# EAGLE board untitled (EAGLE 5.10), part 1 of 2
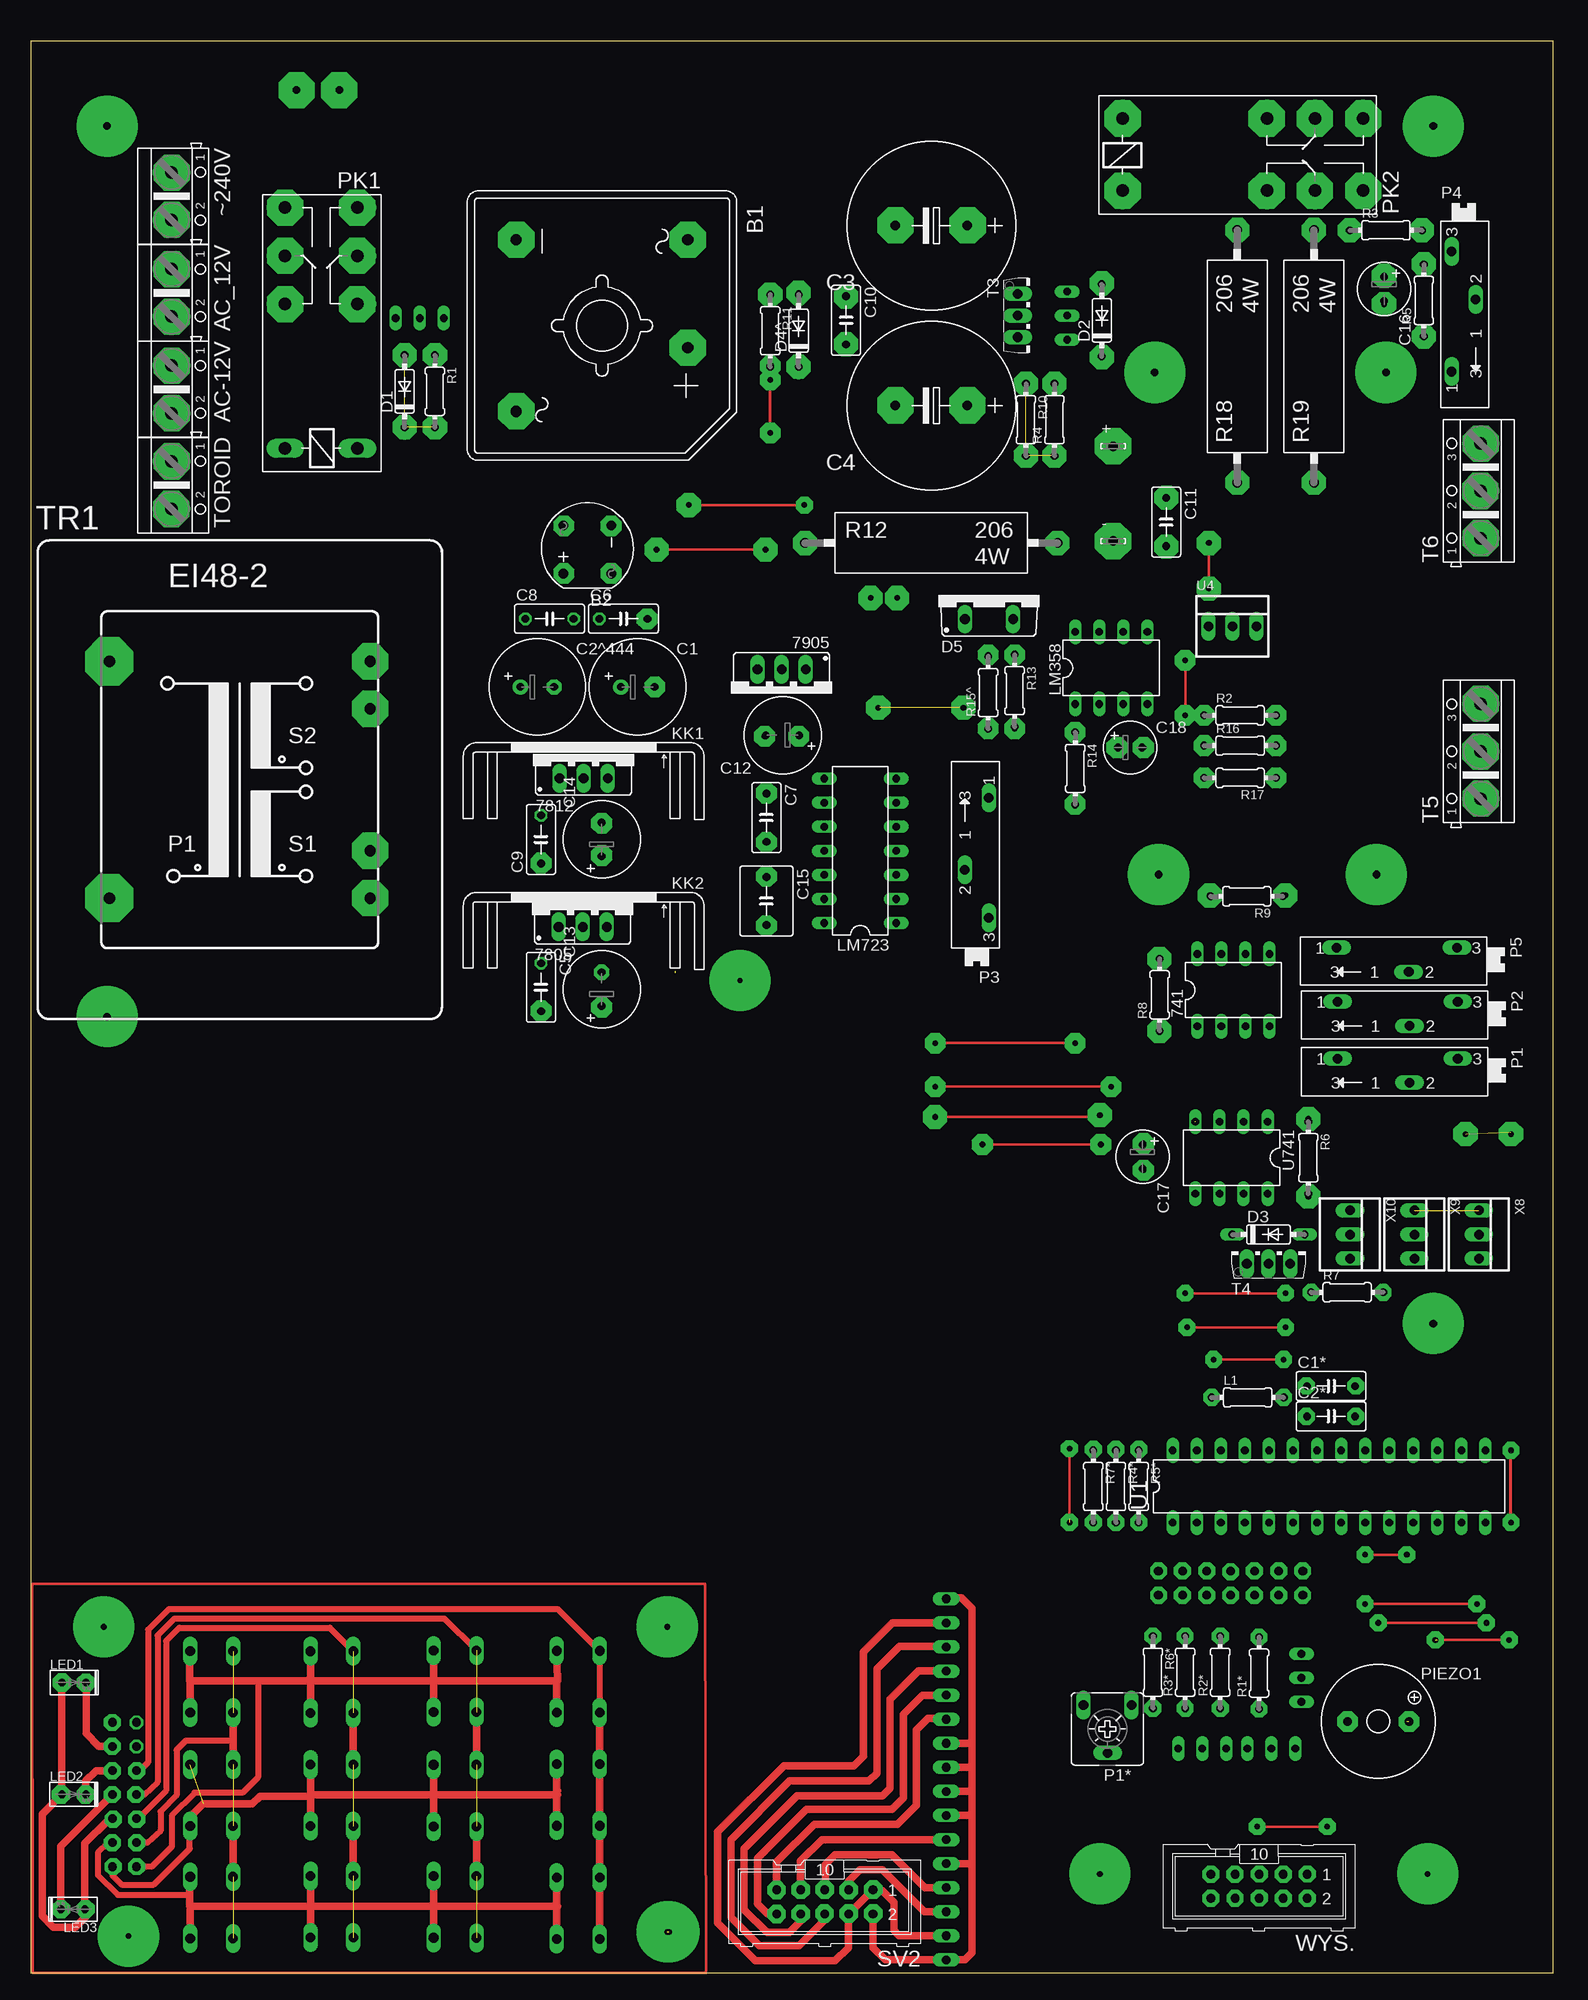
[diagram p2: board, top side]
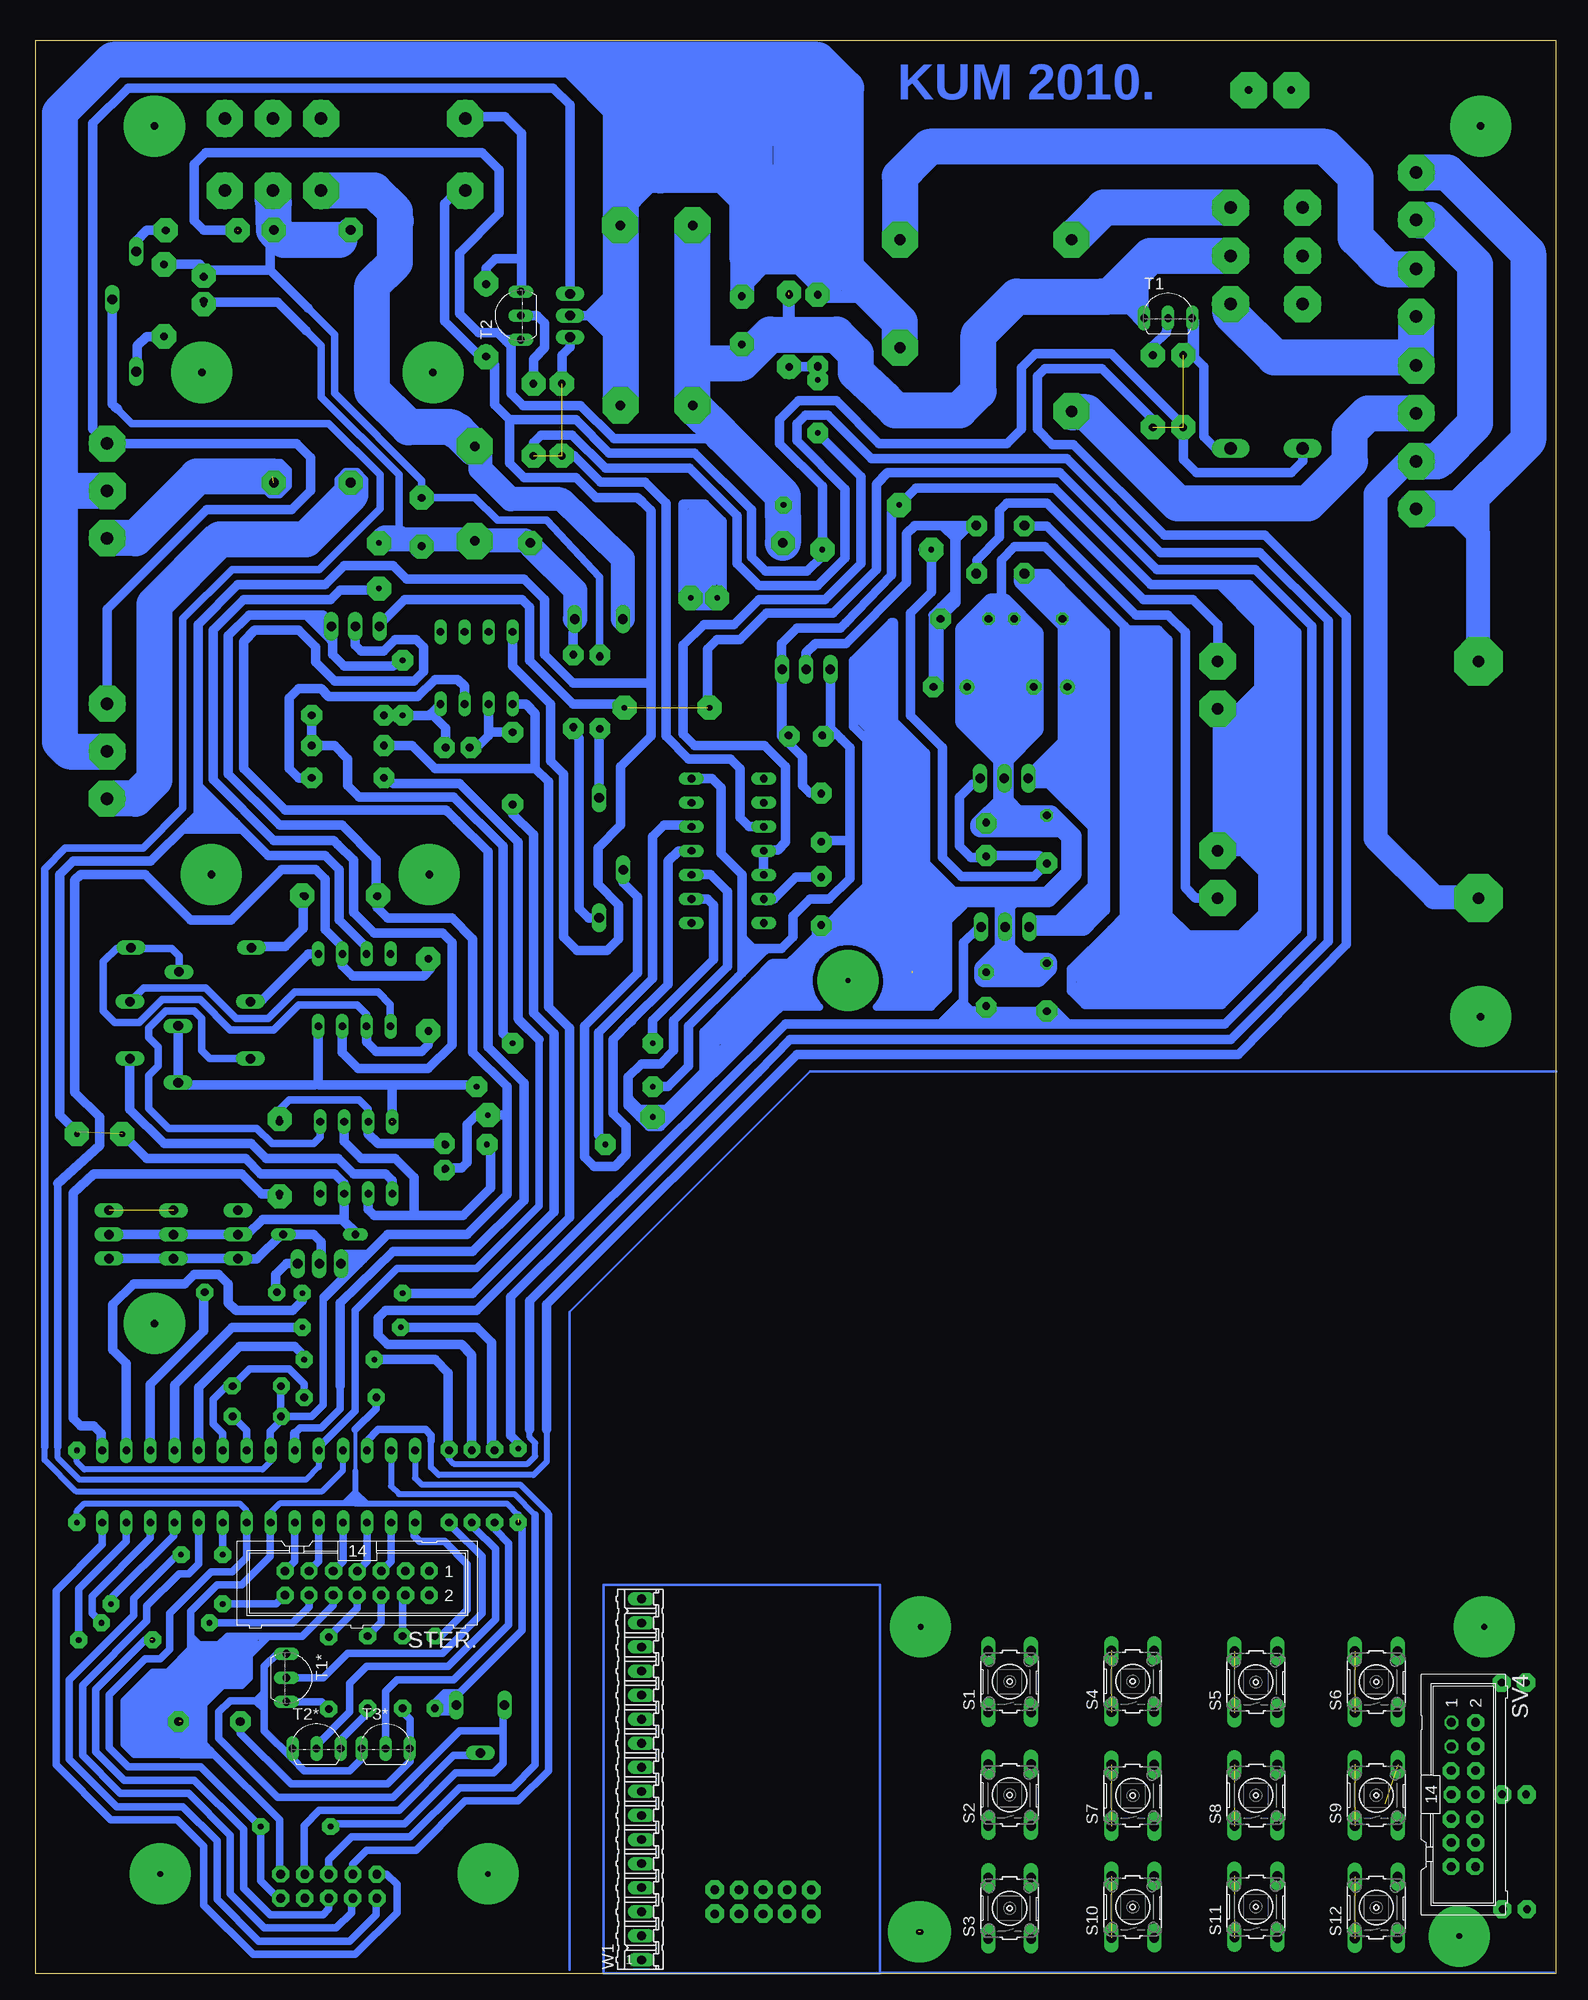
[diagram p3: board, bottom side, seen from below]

Size 160.6 x 204 mm. Coordinates in mm from the lower left corner, seen from the top.
Outline: 0,204 160.6,204 160.6,0 0,0 0,204
Copper layers (1*16): Top 0.035mm / dielectric 1.5mm / Bottom 0.035mm
Design rules "default": minimum track width 10mil, minimum drill 24mil, track to track 8mil, track to pad 8mil, pad to pad 8mil, via to via 8mil, smd to smd 8mil, copper to edge 40mil, drill to drill 8mil, minimum pad ring 10mil, minimum via ring 8mil, stop-mask expansion 4mil, vias tented up to drill 0mil, thermal gap 10mil

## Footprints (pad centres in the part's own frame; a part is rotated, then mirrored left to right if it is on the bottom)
DIL08 = drill 0.813 long: 1 -3.81,-3.81; 2 -1.27,-3.81; 3 1.27,-3.81; 4 3.81,-3.81; 5 3.81,3.81; 6 1.27,3.81; 7 -1.27,3.81; 8 -3.81,3.81
78XXS = drill 1.016 long: GND 0,-2.54; IN -2.54,-2.54; OUT 2.54,-2.54
79XXS = drill 1.016 long: GND -2.54,-2.54; IN 0,-2.54; OUT 2.54,-2.54
LSP10 = drill 1.016 pad 2.159 octagon: MP 0,0
AK500/2 = drill 1.321 long: 1 -2.515,0; 2 2.515,0
FBM = drill 1.194 pad 3 octagon: + 2.337,9.068; - -9.068,-9.068; AC1 -9.068,9.068; AC2 9.068,-9.068
RB1A = drill 1.016 round: + -2.54,2.54 | drill 1.016 octagon: - 2.54,-2.54; AC1 2.54,2.54; AC2 -2.54,-2.54
E3,5-10 = drill 0.813 pad 1.6 round: + -1.778,0 | drill 0.813 pad 1.6 octagon: - 1.778,0
C050-030X075 = drill 0.813 octagon: 1 -2.54,0; 2 2.54,0
E7,5-18 = drill 1.016 pad 3.15 round: + -3.81,0 | drill 1.016 pad 3.15 octagon: - 3.81,0
E3,5-8 = drill 0.813 pad 1.6 round: + -1.778,0 | drill 0.813 pad 1.6 octagon: - 1.778,0
C050-055X075 = drill 0.813 octagon: 1 -2.54,0; 2 2.54,0
E2,5-6 = drill 0.813 pad 1.6 round: + -1.27,0 | drill 0.813 pad 1.6 octagon: - 1.27,0
DO35-7 = drill 0.813 long: A 3.81,0; C -3.81,0
TO220ACS = drill 1.016 long: A 2.54,-2.54; C -2.54,-2.54
0204/7 = drill 0.813 octagon: 1 -3.81,0; 2 3.81,0
LED2X5 = drill 0.813 octagon: A -1.27,0; K 1.27,0
DIL14 = drill 0.813 long: 1 -7.62,-3.81; 2 -5.08,-3.81; 3 -2.54,-3.81; 4 0,-3.81; 5 2.54,-3.81; 6 5.08,-3.81; 7 7.62,-3.81; 8 7.62,3.81; 9 5.08,3.81; 10 2.54,3.81; 11 0,3.81; 12 -2.54,3.81; 13 -5.08,3.81; 14 -7.62,3.81
SP19L = drill 1.016 long: A 5.715,-1.27; E -6.985,-1.27; S -1.905,1.27
CA6V = drill 1.016 long: A -2.54,-2.54; E 2.54,-2.54; S 0,2.54
F/QMBIII = drill 0.914 pad 2.159 octagon: + 3.251,0; - -3.251,0
F4052 = drill 1.321 long: 1 -3.81,3.81; 2 -3.81,-3.81; O1 11.43,-3.81; O2 11.43,3.81; P1 16.51,-3.81; P2 16.51,3.81; S1 21.59,-3.81; S2 21.59,3.81
KH206-8 = drill 1.016 pad 2.54 octagon: 1 -13.335,0; 2 13.335,0
B3F-10XX = drill 1.016 long: 1 -3.251,2.261; 2 3.251,2.261; 3 -3.251,-2.261; 4 3.251,-2.261
ML14 = drill 0.914 octagon: 1 -7.62,-1.27; 2 -7.62,1.27; 3 -5.08,-1.27; 4 -5.08,1.27; 5 -2.54,-1.27; 6 -2.54,1.27; 7 0,-1.27; 8 0,1.27; 9 2.54,-1.27; 10 2.54,1.27; 11 5.08,-1.27; 12 5.08,1.27; 13 7.62,-1.27; 14 7.62,1.27
ML10 = drill 0.914 octagon: 1 -5.08,-1.27; 2 -5.08,1.27; 3 -2.54,-1.27; 4 -2.54,1.27; 5 0,-1.27; 6 0,1.27; 7 2.54,-1.27; 8 2.54,1.27; 9 5.08,-1.27; 10 5.08,1.27
TO92-EBC = drill 0.813 long: B 0,-1.27; C 2.54,-1.27; E -2.54,-1.27
TO126V = drill 1.016 long: 1 -2.286,-1.27; 2 0,-1.27; 3 2.286,-1.27
AK500/3 = drill 1.321 long: 1 -5.004,0; 2 0,0; 3 5.004,0
EI48-2 = drill 1.194 pad 5.08 octagon: 1 -13.767,12.497; 6 -13.767,-12.497 | drill 1.194 pad 3.81 octagon: 7 13.767,-12.497; 8 13.767,-7.493; 11 13.767,7.493; 12 13.767,12.497
DIL28-3 = drill 0.813 long: 1 -16.51,-3.81; 2 -13.97,-3.81; 3 -11.43,-3.81; 4 -8.89,-3.81; 5 -6.35,-3.81; 6 -3.81,-3.81; 7 -1.27,-3.81; 8 1.27,-3.81; 9 3.81,-3.81; 10 6.35,-3.81; 11 8.89,-3.81; 12 11.43,-3.81; 13 13.97,-3.81; 14 16.51,-3.81; 15 16.51,3.81; 16 13.97,3.81; 17 11.43,3.81; 18 8.89,3.81; 19 6.35,3.81; 20 3.81,3.81; 21 1.27,3.81; 22 -1.27,3.81; 23 -3.81,3.81; 24 -6.35,3.81; 25 -8.89,3.81; 26 -11.43,3.81; 27 -13.97,3.81; 28 -16.51,3.81
22-23-2031 = drill 1 long: 1 -2.54,0; 2 0,0; 3 2.54,0
16P = drill 0.914 long: 1 -19.05,0; 2 -16.51,0; 3 -13.97,0; 4 -11.43,0; 5 -8.89,0; 6 -6.35,0; 7 -3.81,0; 8 -1.27,0; 9 1.27,0; 10 3.81,0; 11 6.35,0; 12 8.89,0; 13 11.43,0; 14 13.97,0; 15 16.51,0; 16 19.05,0

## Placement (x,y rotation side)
741  UA741P  [DIL08]  126.9,103.8 0 top
7805  [78XXS]  58.2,113 0 top
7812  [78XXS]  58.3,128.7 0 top
7905  [79XXS]  79.2,135.1 180 top
+  LSP10  [LSP10]  114.2,161.2 0 top
-  LSP10  [LSP10]  114.2,151.2 0 top
AC-12V  [AK500/2]  14.8,167.2 270 top
AC_12V  [AK500/2]  14.8,177.4 270 top
B1  [FBM]  60.24,173.94 270 top
B2  [RB1A]  58.7,150.3 90 top
C1  [E3,5-10]  64,135.8 0 top
C1*  [C050-030X075]  137.2,62 0 top
C2*  [C050-030X075]  137.2,58.8 0 top
C2^444  C2  [E3,5-10]  53.4,135.8 0 top
C3  [E7,5-18]  95,184.5 180 top
C4  [E7,5-18]  95,165.5 180 top
C5  [C050-030X075]  53.8,104.1 270 top
C6  [C050-030X075]  62.5,143 0 top
C7  [C050-030X075]  77.6,122 270 top
C8  [C050-030X075]  54.7,143 0 top
C9  [C050-030X075]  53.8,119.7 90 top
C10  [C050-030X075]  86,174.5 270 top
C11  [C050-030X075]  119.8,153.2 270 top
C12  [E3,5-8]  79.3,130.7 180 top
C13  [E3,5-8]  60.2,103.9 90 top
C14  [E3,5-8]  60.2,119.7 90 top
C15  [C050-055X075]  77.6,113.2 270 top
C16  [E2,5-6]  142.8,177.8 270 top
C17  [E2,5-6]  117.3,86.2 270 top
C18  [E2,5-6]  116,129.4 0 top
D1  1N4148DO35-7  [DO35-7]  39.4,167 90 top
D2  1N4148DO35-7  [DO35-7]  113,174.5 90 top
D3  1N4148DO35-7  [DO35-7]  130.6,78 0 top
D4^  1N4148DO35-7  [DO35-7]  81,173.4 90 top
D5  SR540  [TO220ACS]  101.1,145.5 0 top
KK1  FK209  [FK209]  58.3,128.9 180 top
KK2  FK209  [FK209]  58.3,113.1 180 top
L1  [0204/7]  128.4,60.8 0 top
LED1  zwarcie  [LED2X5]  4.51,30.7 0 top
LED2  przeciazenie  [LED2X5]  4.49,18.9 0 top
LED3  on/off  [LED2X5]  4.39,6.76 180 top
LM358  LM358N  [DIL08]  114,137.8 0 top
LM723  LM723N  [DIL14]  87.5,118.5 90 top
P1  [SP19L]  143.6,95.3 180 top
P1*  [CA6V]  113.6,25.8 180 top
P2  [SP19L]  143.6,101.3 180 top
P3  [SP19L]  99.8,118.4 90 top
P4  [SP19L]  151.2,174.8 270 top
P5  [SP19L]  143.5,107 180 top
PIEZO1  F/QMBIII  [F/QMBIII]  142.2,26.6 0 top
PK1  4052  [F4052]  30.6,164.8 90 top
PK2  4052  [F4052]  119,192 0 top
R1  [0204/7]  42.6,167 270 top
R1*  [0204/7]  129.6,31.7 90 top
R2  [0204/7]  127.6,132.8 0 top
R2*  [0204/7]  125.5,31.8 90 top
R3  [0204/7]  143,184 0 top
R3*  [0204/7]  121.8,31.8 90 top
R4  [0204/7]  108,164 90 top
R4*  [0204/7]  114.5,51.4 270 top
R5  [0204/7]  147,176.6 90 top
R5*  [0204/7]  116.9,51.4 270 top
R6  [0204/7]  134.8,86.1 270 top
R6*  [0204/7]  118.4,31.8 270 top
R7  [0204/7]  138.9,71.9 0 top
R7*  [0204/7]  112.1,51.4 270 top
R8  [0204/7]  119.1,103.3 90 top
R9  [0204/7]  128.3,113.7 180 top
R10  [0204/7]  105,164 270 top
R11  [0204/7]  78,173.4 270 top
R12  [KH206-8]  95,151 0 top
R13  [0204/7]  103.8,135.4 270 top
R14  [0204/7]  110.2,127.2 270 top
R15^  [0204/7]  101,135.2 90 top
R16  [0204/7]  127.6,129.6 0 top
R17  [0204/7]  127.6,126.2 180 top
R18  [KH206-8]  127.3,170.7 90 top
R19  [KH206-8]  135.4,170.7 90 top
S1  [B3F-10XX]  57.73,30.8 90 bottom
S2  [B3F-10XX]  57.73,18.84 90 bottom
S3  [B3F-10XX]  57.73,6.88 90 bottom
S4  [B3F-10XX]  44.73,30.83 90 bottom
S5  [B3F-10XX]  31.73,30.75 90 bottom
S6  [B3F-10XX]  19.03,30.77 90 bottom
S7  [B3F-10XX]  44.73,18.77 90 bottom
S8  [B3F-10XX]  31.73,18.79 90 bottom
S9  [B3F-10XX]  19.03,18.81 90 bottom
S10  [B3F-10XX]  44.73,7.01 90 bottom
S11  [B3F-10XX]  31.73,7.03 90 bottom
S12  [B3F-10XX]  19.03,6.95 90 bottom
STER.  [ML14]  126.6,41.2 180 bottom
SV2  [ML10]  83.76,7.55 180 top
SV4  [ML14]  9.83,18.88 270 bottom
T1  [TO92-EBC]  41,176 0 bottom
T1*  [TO92-EBC]  132.8,31.2 270 bottom
T2  [TO92-EBC]  110.6,175 90 bottom
T2*  [TO92-EBC]  130.9,25 0 bottom
T3  [TO126V]  105.4,175 270 top
T3*  [TO92-EBC]  123.6,25 0 bottom
T4  [TO126V]  130.6,76.2 0 top
T5  [AK500/3]  153,129 90 top
T6  [AK500/3]  153,156.5 90 top
TOROID  [AK500/2]  14.8,157.1 270 top
TR1  [EI48-2]  22,126 0 top
U1  MEGA8-P  [DIL28-3]  137,51.4 0 top
U4  LM35  [22-23-2031]  126.8,142.2 0 top
U741  UA741P  [DIL08]  126.7,86.1 180 top
W1  [16P]  96.59,20.48 90 bottom
WYS.  [ML10]  129.6,9.2 180 top
X8  22-23-2031  [22-23-2031]  152.8,78 270 top
X9  22-23-2031  [22-23-2031]  146,78 270 top
X10  22-23-2031  [22-23-2031]  139.2,78 270 top
~240V  Zas ~220V  [AK500/2]  14.8,187.6 270 top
